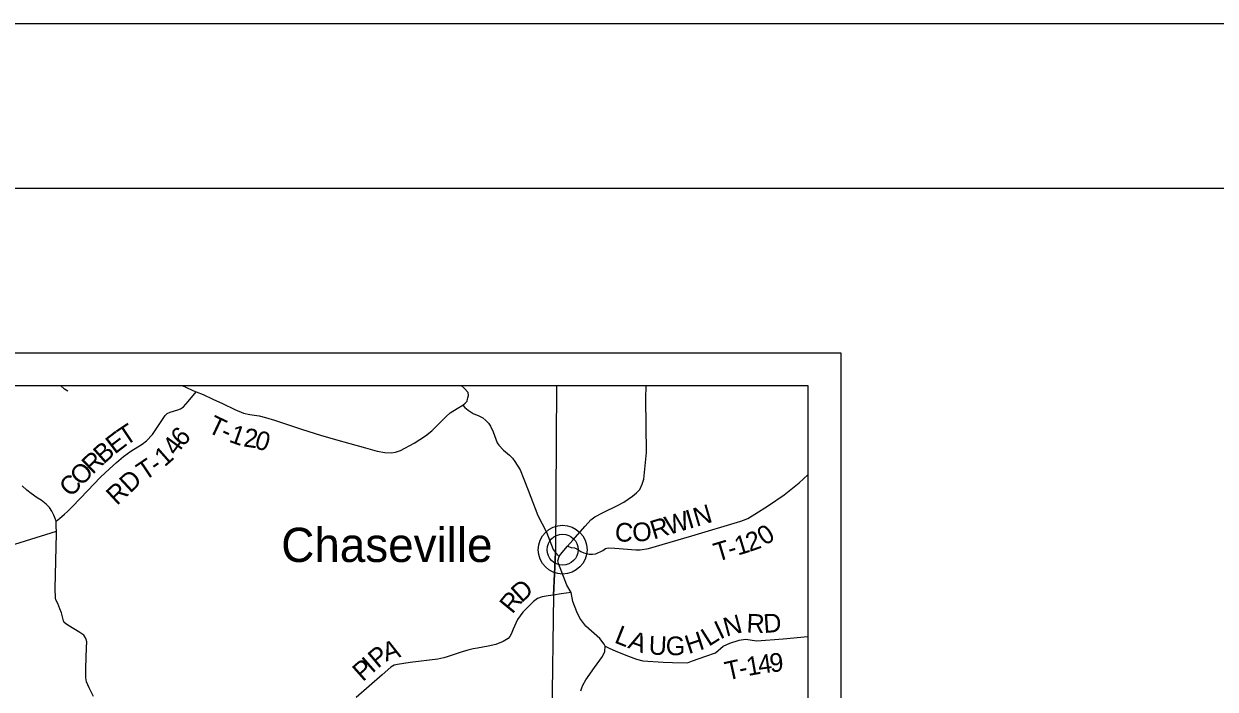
# Model space of a CAD drawing. Extents: x -22 to 431, y -18 to 160.
# Drawn here: x 6.515 to 10.139, y 19.977 to 22 of the extents above; entities that cross this region are included whole.
import ezdxf

# ---------------------------------------------------------------- set-up
doc = ezdxf.new("R2010")
doc.units = 0
for name, color, linetype in [('GM_X_Adjacent_County', 7, 'Continuous'), ('GM_X_Adjacent_County_Text', 7, 'Continuous'), ('GM_X_City_Street', 7, 'Continuous'), ('GM_X_City_Street_Text', 7, 'Continuous'), ('GM_X_County', 7, 'Continuous'), ('GM_X_County_Road', 7, 'Continuous'), ('GM_X_Major_River_Text', 7, 'Continuous'), ('GM_X_Minor_River', 7, 'Continuous'), ('GM_X_Minor_River_Text', 7, 'Continuous'), ('GM_X_Rail_Line', 7, 'Continuous'), ('GM_X_Section', 7, 'Continuous'), ('GM_X_Township', 7, 'Continuous'), ('GM_X_Township_Road', 7, 'Continuous')]:
    doc.layers.add(name, color=color, linetype=linetype)

msp = doc.modelspace()

# ---------------------------------------------------------------- linework, layer by layer
at = {"layer": 'GM_X_Adjacent_County_Text'}
for points in [[(6.727, 19.9547), (6.7137, 19.9814), (6.7056, 19.9994), (6.7035, 20.0116), (6.7031, 20.0408), (6.7058, 20.1041), (6.7064, 20.1212), (6.7046, 20.128), (6.7024, 20.1334), (6.6972, 20.1414), (6.6852, 20.1495), (6.6491, 20.1713), (6.6416, 20.1763), (6.6378, 20.1801), (6.6352, 20.1851), (6.6291, 20.2091), (6.6243, 20.2217), (6.6181, 20.2373), (6.6122, 20.2484), (6.6107, 20.2533), (6.6096, 20.2829), (6.614, 20.4499), (6.6139, 20.4574), (6.6135, 20.4711), (6.613, 20.4874), (6.6097, 20.4955), (6.6057, 20.5065), (6.5997, 20.5187), (6.5927, 20.5294), (6.5826, 20.5398), (6.5679, 20.5514), (6.5555, 20.5591), (6.5371, 20.5723), (6.5244, 20.5819), (6.5097, 20.595)], [(8.18, 20.2712), (8.1498, 20.2671), (8.1261, 20.2632), (8.1094, 20.2612), (8.0912, 20.2576), (8.077, 20.2528), (8.0647, 20.2431), (8.0489, 20.2276), (8.0331, 20.2107), (8.0243, 20.2002), (8.0169, 20.1889), (8.0111, 20.178), (8.0036, 20.1595), (7.997, 20.1444), (7.9931, 20.1376), (7.9877, 20.1313), (7.9732, 20.1223), (7.9511, 20.1131), (7.9271, 20.1077), (7.8952, 20.1021), (7.8819, 20.0996), (7.8659, 20.0953), (7.8484, 20.0909), (7.8027, 20.0752), (7.7928, 20.0723), (7.7746, 20.0687), (7.6899, 20.0577), (7.6515, 20.0521), (7.6416, 20.0499), (7.6313, 20.0444), (7.6045, 20.0208), (7.5259, 19.9516)]]:
    msp.add_lwpolyline(points, dxfattribs=at)
at = {"layer": 'GM_X_County'}
msp.add_lwpolyline([(0, 0), (34, 0), (34, 22), (0, 22)], close=True, dxfattribs=at)
at = {"layer": 'GM_X_County_Road'}
msp.add_lwpolyline([(5.2393, 19.5779), (5.2449, 19.5793), (5.255, 19.5848), (5.2569, 19.6465), (5.2888, 19.6921), (5.6445, 19.9558), (5.8092, 20.1282), (6.093, 20.2952), (6.6139, 20.4574)], dxfattribs=at)
at = {"layer": 'GM_X_Major_River_Text'}
for p, q in [((8.1354, 20.9), (8.1323, 20.3924)), ((8.1323, 20.3924), (8.1261, 20.2632)), ((8.1261, 20.2632), (8.1323, 20.3924)), ((8.1261, 20.2632), (8.1138, 19.3678))]:
    msp.add_line(p, q, dxfattribs=at)
at = {"layer": 'GM_X_Minor_River'}
msp.add_line((8.9, 20.0664), (8.8998, 20.0664), dxfattribs=at)
msp.add_lwpolyline([(6.6489, 20.8834), (6.6388, 20.8896), (6.6265, 20.9)], dxfattribs=at)
at = {"layer": 'GM_X_Minor_River_Text'}
for points in [[(6.9185, 20.77), (6.9451, 20.8091), (6.9509, 20.8148), (6.9604, 20.8188), (6.9836, 20.8265), (6.9916, 20.829), (7.0004, 20.835), (7.0147, 20.8519), (7.0393, 20.8808)], [(6.9968, 20.9), (7.008, 20.8948), (7.0288, 20.8855), (7.0393, 20.8808)], [(7.0393, 20.8808), (7.0601, 20.8729), (7.0902, 20.8589), (7.1196, 20.8456), (7.1565, 20.8273), (7.1829, 20.8159), (7.2026, 20.8119), (7.231, 20.8085), (7.2503, 20.8033), (7.2775, 20.795), (7.3103, 20.7836), (7.362, 20.7662), (7.4168, 20.7496), (7.4629, 20.7364), (7.5067, 20.7245), (7.5543, 20.7106), (7.5898, 20.7003), (7.6129, 20.6969), (7.6326, 20.6956), (7.6455, 20.698), (7.6611, 20.7028), (7.7023, 20.7254), (7.7367, 20.7473), (7.7563, 20.7626), (7.7801, 20.787), (7.7993, 20.8061), (7.8112, 20.817), (7.8326, 20.8304), (7.8502, 20.8408), (7.8565, 20.8335), (7.8663, 20.8254), (7.8817, 20.8157), (7.8991, 20.8082), (7.9107, 20.8016), (7.9201, 20.7943), (7.9287, 20.7855), (7.9343, 20.7763), (7.9424, 20.7595), (7.9505, 20.7374), (7.9549, 20.7263), (7.9601, 20.7187), (7.9743, 20.7037), (7.9919, 20.6883), (8.0013, 20.679), (8.0087, 20.6691), (8.0251, 20.6438), (8.0361, 20.6156), (8.0485, 20.5824), (8.0779, 20.5046), (8.1047, 20.454), (8.1251, 20.402), (8.1323, 20.3924), (8.1433, 20.3804)], [(7.8502, 20.8408), (7.8578, 20.8467), (7.8632, 20.8531), (7.8648, 20.8588), (7.8653, 20.8633), (7.8679, 20.87), (7.8666, 20.8787), (7.8541, 20.8924), (7.8452, 20.9)], [(6.613, 20.4874), (6.6233, 20.4964), (6.6383, 20.5087), (6.6479, 20.5174), (6.6629, 20.5323), (6.7082, 20.5803), (6.7478, 20.6216), (6.7758, 20.6466), (6.7962, 20.6661), (6.8184, 20.6848), (6.8406, 20.7004), (6.875, 20.7224), (6.8884, 20.7317), (6.9057, 20.7512), (6.9185, 20.77), (6.9185, 20.77)], [(8.1686, 20.4114), (8.1801, 20.4081), (8.19, 20.4072), (8.1975, 20.4037), (8.2095, 20.3959), (8.2186, 20.3916), (8.2348, 20.3873), (8.2443, 20.3871), (8.2553, 20.3889), (8.2756, 20.3989), (8.2847, 20.4052), (8.2923, 20.4066), (8.3124, 20.406), (8.3761, 20.401), (8.3901, 20.4008), (8.4155, 20.4051), (8.5468, 20.4436), (8.6957, 20.488), (8.7037, 20.4909), (8.717, 20.4961), (8.738, 20.5095), (8.7801, 20.5355), (8.8275, 20.5675), (8.8735, 20.6041), (8.9, 20.6291)], [(8.2836, 20.1076), (8.2953, 20.1021), (8.3159, 20.093), (8.3543, 20.0772), (8.3784, 20.0687), (8.3977, 20.0633), (8.4597, 20.0588), (8.4881, 20.0581), (8.5338, 20.0573), (8.5492, 20.0627), (8.5897, 20.077), (8.619, 20.088), (8.6424, 20.1082), (8.6621, 20.1173), (8.691, 20.1264), (8.7103, 20.1286), (8.7447, 20.1242), (8.8247, 20.1301), (8.9, 20.1373)]]:
    msp.add_lwpolyline(points, dxfattribs=at)
at = {"layer": 'GM_X_Rail_Line'}
msp.add_lwpolyline([(8.209, 19.9717), (8.2117, 19.9808), (8.2149, 19.9895), (8.2242, 20.0053), (8.2512, 20.0429), (8.2755, 20.0767), (8.2817, 20.0915), (8.2836, 20.1076), (8.2804, 20.1141), (8.2674, 20.131), (8.224, 20.1688), (8.2065, 20.1933), (8.1973, 20.212), (8.1848, 20.2433), (8.18, 20.2712), (8.1665, 20.2929), (8.1408, 20.3593), (8.1394, 20.3676), (8.1433, 20.3804), (8.1476, 20.3869), (8.1686, 20.4114), (8.1846, 20.43), (8.2219, 20.4724), (8.2392, 20.4916), (8.2519, 20.5013), (8.277, 20.5142), (8.3205, 20.5357), (8.34, 20.5453), (8.3668, 20.5635), (8.3787, 20.5744), (8.3891, 20.5845), (8.3961, 20.6007), (8.4008, 20.6151), (8.4091, 20.6966), (8.407, 20.8594), (8.4083, 20.9)], dxfattribs=at)
at = {"layer": 'GM_X_Section'}
for p, q in [((2, 21), (9, 21)), ((9, 21), (9, 14)), ((4.7256, 20.9), (8.9, 20.9)), ((8.9, 20.9), (8.9, 14.1))]:
    msp.add_line(p, q, dxfattribs=at)
at = {"layer": 'GM_X_Township'}
msp.add_lwpolyline([(1.5, 21.5), (33.5, 21.5), (33.5, 0.5), (1.5, 0.5)], close=True, dxfattribs=at)
at = {"layer": 'GM_X_Township_Road'}
for radius in [0.0744, 0.0472]:
    msp.add_circle((8.1538, 20.4012), radius, dxfattribs=at)

# ---------------------------------------------------------------- texts
at = {"layer": 'GM_X_Adjacent_County'}
msp.add_text('Chaseville', height=0.10417, rotation=0, dxfattribs=at).set_placement((7.2979, 20.3637))
at = {"layer": 'GM_X_City_Street'}
for s, rotation, p in [('D', 42.0803, (8.0287, 20.2379)), ('R', 50.7251, (8.0008, 20.2034)), ('A', 18.0444, (7.6162, 20.0604)), ('P', 40.0246, (7.5918, 20.0385)), ('P', 41.4094, (7.5458, 19.998)), ('I', 41.3438, (7.5746, 20.0234))]:
    msp.add_text(s, height=0.0568, rotation=rotation, dxfattribs=at).set_placement(p)
at = {"layer": 'GM_X_City_Street_Text'}
for s, height, rotation, p in [('T', 0.0568, 334.7364, (7.0706, 20.7602)), ('T', 0.0568, 33.5878, (6.8245, 20.715)), ('6', 0.0568, 48.181, (6.9981, 20.7114)), ('1', 0.0568, 340.5729, (7.1361, 20.7299)), ('2', 0.0568, 352.1052, (7.1812, 20.7153)), ('B', 0.0568, 41.5924, (6.7575, 20.6596)), ('E', 0.0568, 37.3653, (6.7915, 20.6898)), ('4', 0.0568, 54.0246, (6.9785, 20.6843)), ('-', 0.0568, 335.3637, (7.1096, 20.7417)), ('0', 0.0568, 343.4942, (7.2136, 20.711)), ('R', 0.0568, 43.5482, (6.724, 20.6277)), ('1', 0.0568, 41.4337, (6.9431, 20.6511)), ('O', 0.0568, 46.0973, (6.6898, 20.5922)), ('T', 0.0568, 34.0395, (6.8825, 20.609)), ('-', 0.0568, 35.0271, (6.9186, 20.6334)), ('C', 0.0568, 46.565, (6.6578, 20.5584)), ('RD', 0.05682, 42.8433, (6.7977, 20.5338)), ('W', 0.0568, 16.4687, (8.4751, 20.4454)), ('I', 0.0568, 16.4697, (8.5382, 20.4641)), ('N', 0.0568, 16.4648, (8.5606, 20.4707)), ('C', 0.0568, 355.1271, (8.3108, 20.4282)), ('O', 0.0568, 5.6073, (8.3686, 20.4243)), ('R', 0.0568, 17.2436, (8.4307, 20.4317)), ('0', 0.0568, 32.7325, (8.7686, 20.4119)), ('1', 0.0568, 16.945, (8.6866, 20.383)), ('2', 0.0568, 19.117, (8.7224, 20.394)), ('T', 0.0568, 16.746, (8.6234, 20.364)), ('-', 0.0568, 16.769, (8.6641, 20.3763)), ('N', 0.0568, 15.0877, (8.6513, 20.1365)), ('R', 0.0568, 357.4036, (8.7124, 20.1497)), ('D', 0.0568, 4.166, (8.7664, 20.1477)), ('L', 0.0568, 338.3745, (8.3083, 20.1197)), ('H', 0.0568, 18.2227, (8.5371, 20.0832)), ('L', 0.0568, 32.5512, (8.5985, 20.1055)), ('I', 0.0568, 25.406, (8.6327, 20.1274)), ('A', 0.0568, 340.1042, (8.3496, 20.1034)), ('U', 0.0568, 357.2322, (8.4147, 20.0828)), ('G', 0.0568, 359.8122, (8.4675, 20.0803)), ('1', 0.0568, 10.027, (8.7179, 20.017)), ('4', 0.0568, 8.2192, (8.7519, 20.023)), ('9', 0.0568, 5.9431, (8.786, 20.0279)), ('T', 0.0568, 12.5279, (8.6542, 20.0031)), ('-', 0.0568, 11.7845, (8.6955, 20.0123))]:
    msp.add_text(s, height=height, rotation=rotation, dxfattribs=at).set_placement(p)

doc.saveas('drawing.dxf')
